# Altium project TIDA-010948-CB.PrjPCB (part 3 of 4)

## Sheet TIDA-010948-CB-PWM.SchDoc
size 431 x 279 mm; Date: Not shown in title block; ApprovedBy: Not shown in title block; CheckedBy: Not shown in title block; Author: Not shown in title block; CompanyName: Not shown in title block; Engineer: Not shown in title block; Organization: Not shown in title block; Address1: Not shown in title block; Address2: Not shown in title block; Address3: Not shown in title block; Address4: Not shown in title block; DocumentNumber: 7; Revision: Use project parameter SCH_Rev; SheetNumber: 7; SheetTotal: 11; PageSetup: Record=PageOptions¦CenterHorizontal=True¦CenterVertical=True¦PrintScale=1.00¦XCorrection=1.00¦YCorrection=1.00¦PrintKind=0¦BorderSize=5000000¦LeftOffset=0¦BottomOffset=0¦Orientation=2¦PaperLength=1000¦PaperWidth=1000¦Scale=100¦PaperSource=15¦PrintQuality=600¦MediaType=1¦DitherType=10¦PaperKind=Letter¦PrintScaleMode=1
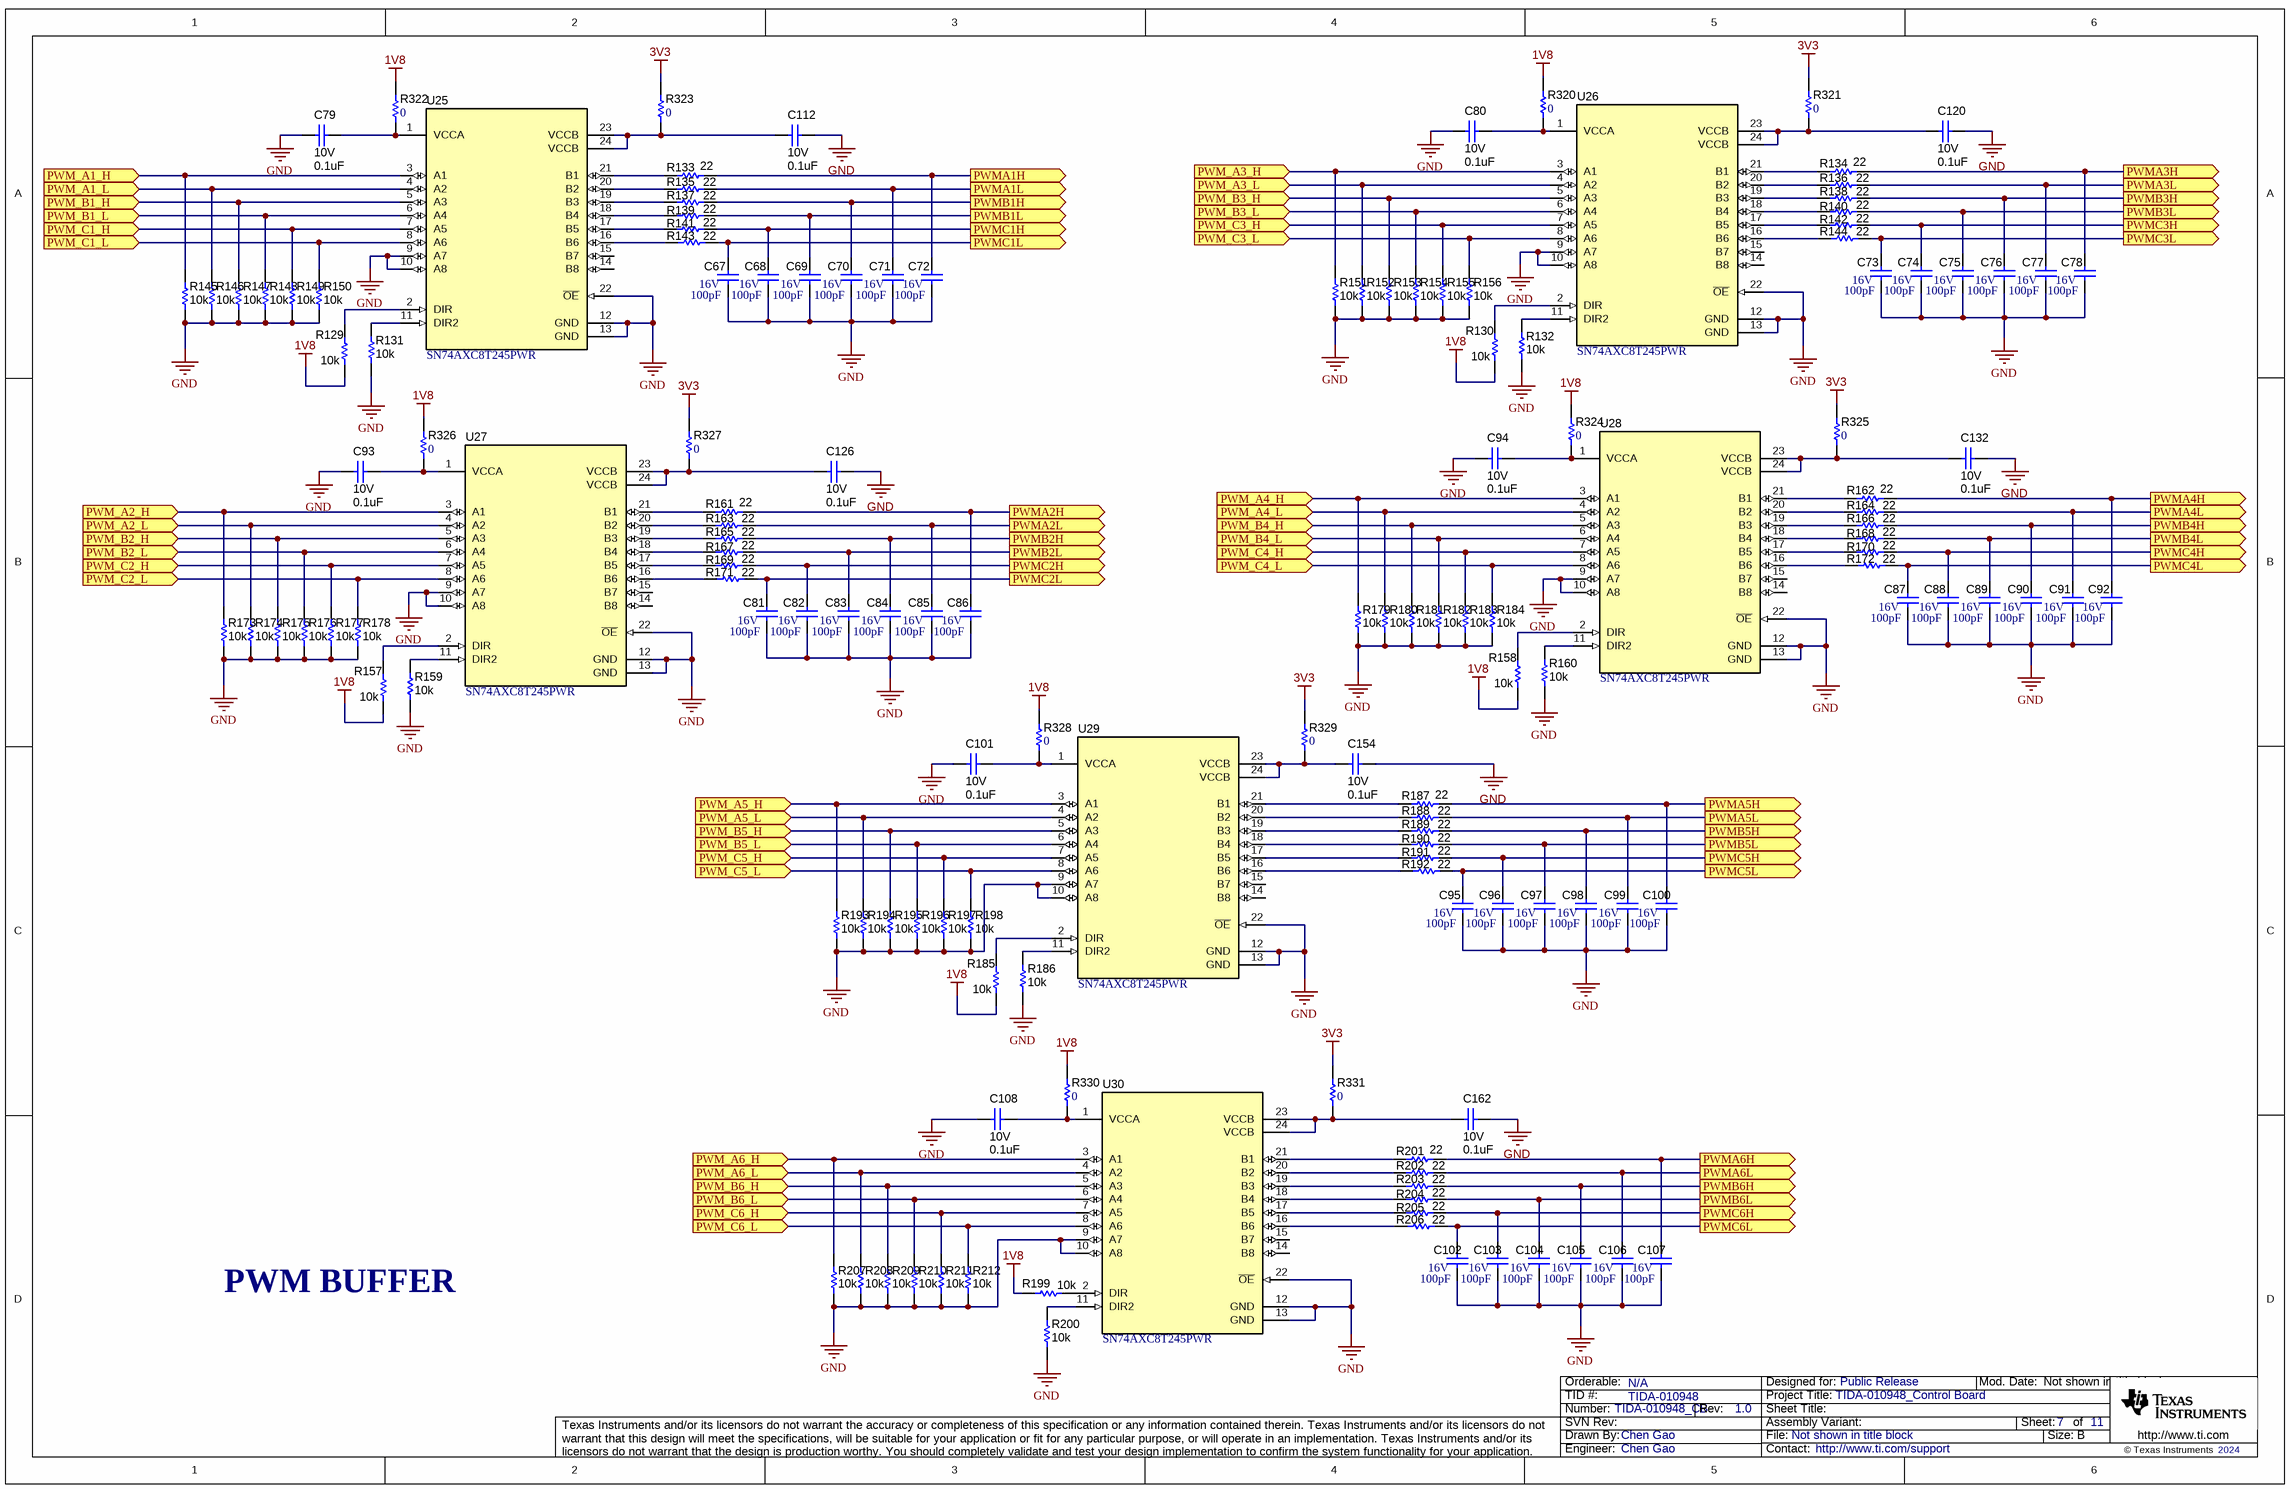
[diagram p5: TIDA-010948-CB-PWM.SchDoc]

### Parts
C67  VDC_V: 16V  ValueDisplayed: 100pF  [0402]  (hidden comment: 0402YC101KAT2A)
C68  VDC_V: 16V  ValueDisplayed: 100pF  [0402]  (hidden comment: 0402YC101KAT2A)
C69  VDC_V: 16V  ValueDisplayed: 100pF  [0402]  (hidden comment: 0402YC101KAT2A)
C70  VDC_V: 16V  ValueDisplayed: 100pF  [0402]  (hidden comment: 0402YC101KAT2A)
C71  VDC_V: 16V  ValueDisplayed: 100pF  [0402]  (hidden comment: 0402YC101KAT2A)
C72  VDC_V: 16V  ValueDisplayed: 100pF  [0402]  (hidden comment: 0402YC101KAT2A)
C73  VDC_V: 16V  ValueDisplayed: 100pF  [0402]  (hidden comment: 0402YC101KAT2A)
C74  VDC_V: 16V  ValueDisplayed: 100pF  [0402]  (hidden comment: 0402YC101KAT2A)
C75  VDC_V: 16V  ValueDisplayed: 100pF  [0402]  (hidden comment: 0402YC101KAT2A)
C76  VDC_V: 16V  ValueDisplayed: 100pF  [0402]  (hidden comment: 0402YC101KAT2A)
C77  VDC_V: 16V  ValueDisplayed: 100pF  [0402]  (hidden comment: 0402YC101KAT2A)
C78  VDC_V: 16V  ValueDisplayed: 100pF  [0402]  (hidden comment: 0402YC101KAT2A)
C79  VDC_V: 10V  ValueDisplayed: 0.1uF  [0402]  (hidden comment: GRM155R71A104KA01D)
C80  VDC_V: 10V  ValueDisplayed: 0.1uF  [0402]  (hidden comment: GRM155R71A104KA01D)
C81  VDC_V: 16V  ValueDisplayed: 100pF  [0402]  (hidden comment: 0402YC101KAT2A)
C82  VDC_V: 16V  ValueDisplayed: 100pF  [0402]  (hidden comment: 0402YC101KAT2A)
C83  VDC_V: 16V  ValueDisplayed: 100pF  [0402]  (hidden comment: 0402YC101KAT2A)
C84  VDC_V: 16V  ValueDisplayed: 100pF  [0402]  (hidden comment: 0402YC101KAT2A)
C85  VDC_V: 16V  ValueDisplayed: 100pF  [0402]  (hidden comment: 0402YC101KAT2A)
C86  VDC_V: 16V  ValueDisplayed: 100pF  [0402]  (hidden comment: 0402YC101KAT2A)
C87  VDC_V: 16V  ValueDisplayed: 100pF  [0402]  (hidden comment: 0402YC101KAT2A)
C88  VDC_V: 16V  ValueDisplayed: 100pF  [0402]  (hidden comment: 0402YC101KAT2A)
C89  VDC_V: 16V  ValueDisplayed: 100pF  [0402]  (hidden comment: 0402YC101KAT2A)
C90  VDC_V: 16V  ValueDisplayed: 100pF  [0402]  (hidden comment: 0402YC101KAT2A)
C91  VDC_V: 16V  ValueDisplayed: 100pF  [0402]  (hidden comment: 0402YC101KAT2A)
C92  VDC_V: 16V  ValueDisplayed: 100pF  [0402]  (hidden comment: 0402YC101KAT2A)
C93  VDC_V: 10V  ValueDisplayed: 0.1uF  [0402]  (hidden comment: GRM155R71A104KA01D)
C94  VDC_V: 10V  ValueDisplayed: 0.1uF  [0402]  (hidden comment: GRM155R71A104KA01D)
C95  VDC_V: 16V  ValueDisplayed: 100pF  [0402]  (hidden comment: 0402YC101KAT2A)
C96  VDC_V: 16V  ValueDisplayed: 100pF  [0402]  (hidden comment: 0402YC101KAT2A)
C97  VDC_V: 16V  ValueDisplayed: 100pF  [0402]  (hidden comment: 0402YC101KAT2A)
C98  VDC_V: 16V  ValueDisplayed: 100pF  [0402]  (hidden comment: 0402YC101KAT2A)
C99  VDC_V: 16V  ValueDisplayed: 100pF  [0402]  (hidden comment: 0402YC101KAT2A)
C100  VDC_V: 16V  ValueDisplayed: 100pF  [0402]  (hidden comment: 0402YC101KAT2A)
C101  VDC_V: 10V  ValueDisplayed: 0.1uF  [0402]  (hidden comment: GRM155R71A104KA01D)
C102  VDC_V: 16V  ValueDisplayed: 100pF  [0402]  (hidden comment: 0402YC101KAT2A)
C103  VDC_V: 16V  ValueDisplayed: 100pF  [0402]  (hidden comment: 0402YC101KAT2A)
C104  VDC_V: 16V  ValueDisplayed: 100pF  [0402]  (hidden comment: 0402YC101KAT2A)
C105  VDC_V: 16V  ValueDisplayed: 100pF  [0402]  (hidden comment: 0402YC101KAT2A)
C106  VDC_V: 16V  ValueDisplayed: 100pF  [0402]  (hidden comment: 0402YC101KAT2A)
C107  VDC_V: 16V  ValueDisplayed: 100pF  [0402]  (hidden comment: 0402YC101KAT2A)
C108  VDC_V: 10V  ValueDisplayed: 0.1uF  [0402]  (hidden comment: GRM155R71A104KA01D)
C112  VDC_V: 10V  ValueDisplayed: 0.1uF  [0402]  (hidden comment: GRM155R71A104KA01D)
C120  VDC_V: 10V  ValueDisplayed: 0.1uF  [0402]  (hidden comment: GRM155R71A104KA01D)
C126  VDC_V: 10V  ValueDisplayed: 0.1uF  [0402]  (hidden comment: GRM155R71A104KA01D)
C132  VDC_V: 10V  ValueDisplayed: 0.1uF  [0402]  (hidden comment: GRM155R71A104KA01D)
C154  VDC_V: 10V  ValueDisplayed: 0.1uF  [0402]  (hidden comment: GRM155R71A104KA01D)
C162  VDC_V: 10V  ValueDisplayed: 0.1uF  [0402]  (hidden comment: GRM155R71A104KA01D)
R129  ValueDisplayed: 10k  [0402]  (hidden comment: Resistor)
R130  ValueDisplayed: 10k  [0402]  (hidden comment: Resistor)
R131  ValueDisplayed: 10k  [0402]  (hidden comment: Resistor)
R132  ValueDisplayed: 10k  [0402]  (hidden comment: Resistor)
R133  ValueDisplayed: 22  [0402]  (hidden comment: CRCW040222R0JNED)
R134  ValueDisplayed: 22  [0402]  (hidden comment: CRCW040222R0JNED)
R135  ValueDisplayed: 22  [0402]  (hidden comment: CRCW040222R0JNED)
R136  ValueDisplayed: 22  [0402]  (hidden comment: CRCW040222R0JNED)
R137  ValueDisplayed: 22  [0402]  (hidden comment: CRCW040222R0JNED)
R138  ValueDisplayed: 22  [0402]  (hidden comment: CRCW040222R0JNED)
R139  ValueDisplayed: 22  [0402]  (hidden comment: CRCW040222R0JNED)
R140  ValueDisplayed: 22  [0402]  (hidden comment: CRCW040222R0JNED)
R141  ValueDisplayed: 22  [0402]  (hidden comment: CRCW040222R0JNED)
R142  ValueDisplayed: 22  [0402]  (hidden comment: CRCW040222R0JNED)
R143  ValueDisplayed: 22  [0402]  (hidden comment: CRCW040222R0JNED)
R144  ValueDisplayed: 22  [0402]  (hidden comment: CRCW040222R0JNED)
R145  ValueDisplayed: 10k  [0402]  (hidden comment: Resistor)
R146  ValueDisplayed: 10k  [0402]  (hidden comment: Resistor)
R147  ValueDisplayed: 10k  [0402]  (hidden comment: Resistor)
R148  ValueDisplayed: 10k  [0402]  (hidden comment: Resistor)
R149  ValueDisplayed: 10k  [0402]  (hidden comment: Resistor)
R150  ValueDisplayed: 10k  [0402]  (hidden comment: Resistor)
R151  ValueDisplayed: 10k  [0402]  (hidden comment: Resistor)
R152  ValueDisplayed: 10k  [0402]  (hidden comment: Resistor)
R153  ValueDisplayed: 10k  [0402]  (hidden comment: Resistor)
R154  ValueDisplayed: 10k  [0402]  (hidden comment: Resistor)
R155  ValueDisplayed: 10k  [0402]  (hidden comment: Resistor)
R156  ValueDisplayed: 10k  [0402]  (hidden comment: Resistor)
R157  ValueDisplayed: 10k  [0402]  (hidden comment: Resistor)
R158  ValueDisplayed: 10k  [0402]  (hidden comment: Resistor)
R159  ValueDisplayed: 10k  [0402]  (hidden comment: Resistor)
R160  ValueDisplayed: 10k  [0402]  (hidden comment: Resistor)
R161  ValueDisplayed: 22  [0402]  (hidden comment: CRCW040222R0JNED)
R162  ValueDisplayed: 22  [0402]  (hidden comment: CRCW040222R0JNED)
R163  ValueDisplayed: 22  [0402]  (hidden comment: CRCW040222R0JNED)
R164  ValueDisplayed: 22  [0402]  (hidden comment: CRCW040222R0JNED)
R165  ValueDisplayed: 22  [0402]  (hidden comment: CRCW040222R0JNED)
R166  ValueDisplayed: 22  [0402]  (hidden comment: CRCW040222R0JNED)
R167  ValueDisplayed: 22  [0402]  (hidden comment: CRCW040222R0JNED)
R168  ValueDisplayed: 22  [0402]  (hidden comment: CRCW040222R0JNED)
R169  ValueDisplayed: 22  [0402]  (hidden comment: CRCW040222R0JNED)
R170  ValueDisplayed: 22  [0402]  (hidden comment: CRCW040222R0JNED)
R171  ValueDisplayed: 22  [0402]  (hidden comment: CRCW040222R0JNED)
R172  ValueDisplayed: 22  [0402]  (hidden comment: CRCW040222R0JNED)
R173  ValueDisplayed: 10k  [0402]  (hidden comment: Resistor)
R174  ValueDisplayed: 10k  [0402]  (hidden comment: Resistor)
R175  ValueDisplayed: 10k  [0402]  (hidden comment: Resistor)
R176  ValueDisplayed: 10k  [0402]  (hidden comment: Resistor)
R177  ValueDisplayed: 10k  [0402]  (hidden comment: Resistor)
R178  ValueDisplayed: 10k  [0402]  (hidden comment: Resistor)
R179  ValueDisplayed: 10k  [0402]  (hidden comment: Resistor)
R180  ValueDisplayed: 10k  [0402]  (hidden comment: Resistor)
R181  ValueDisplayed: 10k  [0402]  (hidden comment: Resistor)
R182  ValueDisplayed: 10k  [0402]  (hidden comment: Resistor)
R183  ValueDisplayed: 10k  [0402]  (hidden comment: Resistor)
R184  ValueDisplayed: 10k  [0402]  (hidden comment: Resistor)
R185  ValueDisplayed: 10k  [0402]  (hidden comment: Resistor)
R186  ValueDisplayed: 10k  [0402]  (hidden comment: Resistor)
R187  ValueDisplayed: 22  [0402]  (hidden comment: CRCW040222R0JNED)
R188  ValueDisplayed: 22  [0402]  (hidden comment: CRCW040222R0JNED)
R189  ValueDisplayed: 22  [0402]  (hidden comment: CRCW040222R0JNED)
R190  ValueDisplayed: 22  [0402]  (hidden comment: CRCW040222R0JNED)
R191  ValueDisplayed: 22  [0402]  (hidden comment: CRCW040222R0JNED)
R192  ValueDisplayed: 22  [0402]  (hidden comment: CRCW040222R0JNED)
R193  ValueDisplayed: 10k  [0402]  (hidden comment: Resistor)
R194  ValueDisplayed: 10k  [0402]  (hidden comment: Resistor)
R195  ValueDisplayed: 10k  [0402]  (hidden comment: Resistor)
R196  ValueDisplayed: 10k  [0402]  (hidden comment: Resistor)
R197  ValueDisplayed: 10k  [0402]  (hidden comment: Resistor)
R198  ValueDisplayed: 10k  [0402]  (hidden comment: Resistor)
R199  ValueDisplayed: 10k  [0402]  (hidden comment: Resistor)
R200  ValueDisplayed: 10k  [0402]  (hidden comment: Resistor)
R201  ValueDisplayed: 22  [0402]  (hidden comment: CRCW040222R0JNED)
R202  ValueDisplayed: 22  [0402]  (hidden comment: CRCW040222R0JNED)
R203  ValueDisplayed: 22  [0402]  (hidden comment: CRCW040222R0JNED)
R204  ValueDisplayed: 22  [0402]  (hidden comment: CRCW040222R0JNED)
R205  ValueDisplayed: 22  [0402]  (hidden comment: CRCW040222R0JNED)
R206  ValueDisplayed: 22  [0402]  (hidden comment: CRCW040222R0JNED)
R207  ValueDisplayed: 10k  [0402]  (hidden comment: Resistor)
R208  ValueDisplayed: 10k  [0402]  (hidden comment: Resistor)
R209  ValueDisplayed: 10k  [0402]  (hidden comment: Resistor)
R210  ValueDisplayed: 10k  [0402]  (hidden comment: Resistor)
R211  ValueDisplayed: 10k  [0402]  (hidden comment: Resistor)
R212  ValueDisplayed: 10k  [0402]  (hidden comment: Resistor)
R320  ValueDisplayed: 0  [0402L]  (hidden comment: ERJ-2GE0R00X)
R321  ValueDisplayed: 0  [0402L]  (hidden comment: ERJ-2GE0R00X)
R322  ValueDisplayed: 0  [0402L]  (hidden comment: ERJ-2GE0R00X)
R323  ValueDisplayed: 0  [0402L]  (hidden comment: ERJ-2GE0R00X)
R324  ValueDisplayed: 0  [0402L]  (hidden comment: ERJ-2GE0R00X)
R325  ValueDisplayed: 0  [0402L]  (hidden comment: ERJ-2GE0R00X)
R326  ValueDisplayed: 0  [0402L]  (hidden comment: ERJ-2GE0R00X)
R327  ValueDisplayed: 0  [0402L]  (hidden comment: ERJ-2GE0R00X)
R328  ValueDisplayed: 0  [0402L]  (hidden comment: ERJ-2GE0R00X)
R329  ValueDisplayed: 0  [0402L]  (hidden comment: ERJ-2GE0R00X)
R330  ValueDisplayed: 0  [0402L]  (hidden comment: ERJ-2GE0R00X)
R331  ValueDisplayed: 0  [0402L]  (hidden comment: ERJ-2GE0R00X)
U25  SN74AXC8T245PWR  [PW0024A_N]
U26  SN74AXC8T245PWR  [PW0024A_N]
U27  SN74AXC8T245PWR  [PW0024A_N]
U28  SN74AXC8T245PWR  [PW0024A_N]
U29  SN74AXC8T245PWR  [PW0024A_N]
U30  SN74AXC8T245PWR  [PW0024A_N]

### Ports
PWM_A1_H (in), PWM_A1_L (in), PWM_A2_H (in), PWM_A2_L (in), PWM_A3_H (in), PWM_A3_L (in), PWM_A4_H (in), PWM_A4_L (in), PWM_A5_H (in), PWM_A5_L (in), PWM_A6_H (in), PWM_A6_L (in), PWM_B1_H (in), PWM_B1_L (in), PWM_B2_H (in), PWM_B2_L (in), PWM_B3_H (in), PWM_B3_L (in), PWM_B4_H (in), PWM_B4_L (in), PWM_B5_H (in), PWM_B5_L (in), PWM_B6_H (in), PWM_B6_L (in), PWM_C1_H (in), PWM_C1_L (in), PWM_C2_H (in), PWM_C2_L (in), PWM_C3_H (in), PWM_C3_L (in), PWM_C4_H (in), PWM_C4_L (in), PWM_C5_H (in), PWM_C5_L (in), PWM_C6_H (in), PWM_C6_L (in), PWMA1H (out), PWMA1L (out), PWMA2H (out), PWMA2L (out), PWMA3H (out), PWMA3L (out), PWMA4H (out), PWMA4L (out), PWMA5H (out), PWMA5L (out), PWMA6H (out), PWMA6L (out), PWMB1H (out), PWMB1L (out), PWMB2H (out), PWMB2L (out), PWMB3H (out), PWMB3L (out), PWMB4H (out), PWMB4L (out), PWMB5H (out), PWMB5L (out), PWMB6H (out), PWMB6L (out), PWMC1H (out), PWMC1L (out), PWMC2H (out), PWMC2L (out), PWMC3H (out), PWMC3L (out), PWMC4H (out), PWMC4L (out), PWMC5H (out), PWMC5L (out), PWMC6H (out), PWMC6L (out)

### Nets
1V8: R129.1 R130.1 R157.1 R158.1 R185.1 R199.1 R320.2 R322.2 R324.2 R326.2 R328.2 R330.2
3V3: R321.2 R323.2 R325.2 R327.2 R329.2 R331.2
GND: C67.2 C68.2 C69.2 C70.2 C71.2 C72.2 C73.2 C74.2 C75.2 C76.2 C77.2 C78.2 C79.1 C80.1 C81.2 C82.2 C83.2 C84.2 C85.2 C86.2 C87.2 C88.2 C89.2 C90.2 C91.2 C92.2 C93.1 C94.1 C95.2 C96.2 C97.2 C98.2 C99.2 C100.2 C101.1 C102.2 C103.2 C104.2 C105.2 C106.2 C107.2 C108.1 C112.2 C120.2 C126.2 C132.2 C154.2 C162.2 R131.2 R132.2 R145.2 R146.2 R147.2 R148.2 R149.2 R150.2 R151.2 R152.2 R153.2 R154.2 R155.2 R156.2 R159.2 R160.2 R173.2 R174.2 R175.2 R176.2 R177.2 R178.2 R179.2 R180.2 R181.2 R182.2 R183.2 R184.2 R186.2 R193.2 R194.2 R195.2 R196.2 R197.2 R198.2 R200.2 R207.2 R208.2 R209.2 R210.2 R211.2 R212.2 U25.9(A7) U25.10(A8) U25.12(GND) U25.13(GND) U25.22(~{OE}) U26.9(A7) U26.10(A8) U26.12(GND) U26.13(GND) U26.22(~{OE}) U27.9(A7) U27.10(A8) U27.12(GND) U27.13(GND) U27.22(~{OE}) U28.9(A7) U28.10(A8) U28.12(GND) U28.13(GND) U28.22(~{OE}) U29.9(A7) U29.10(A8) U29.12(GND) U29.13(GND) U29.22(~{OE}) U30.9(A7) U30.10(A8) U30.12(GND) U30.13(GND) U30.22(~{OE})
PWM_A1_H: R145.1 U25.3(A1) ; port PWM_A1_H
PWM_A1_L: R146.1 U25.4(A2) ; port PWM_A1_L
PWM_A2_H: R173.1 U27.3(A1) ; port PWM_A2_H
PWM_A2_L: R174.1 U27.4(A2) ; port PWM_A2_L
PWM_A3_H: R151.1 U26.3(A1) ; port PWM_A3_H
PWM_A3_L: R152.1 U26.4(A2) ; port PWM_A3_L
PWM_A4_H: R179.1 U28.3(A1) ; port PWM_A4_H
PWM_A4_L: R180.1 U28.4(A2) ; port PWM_A4_L
PWM_A5_H: R193.1 U29.3(A1) ; port PWM_A5_H
PWM_A5_L: R194.1 U29.4(A2) ; port PWM_A5_L
PWM_A6_H: R207.1 U30.3(A1) ; port PWM_A6_H
PWM_A6_L: R208.1 U30.4(A2) ; port PWM_A6_L
PWM_B1_H: R147.1 U25.5(A3) ; port PWM_B1_H
PWM_B1_L: R148.1 U25.6(A4) ; port PWM_B1_L
PWM_B2_H: R175.1 U27.5(A3) ; port PWM_B2_H
PWM_B2_L: R176.1 U27.6(A4) ; port PWM_B2_L
PWM_B3_H: R153.1 U26.5(A3) ; port PWM_B3_H
PWM_B3_L: R154.1 U26.6(A4) ; port PWM_B3_L
PWM_B4_H: R181.1 U28.5(A3) ; port PWM_B4_H
PWM_B4_L: R182.1 U28.6(A4) ; port PWM_B4_L
PWM_B5_H: R195.1 U29.5(A3) ; port PWM_B5_H
PWM_B5_L: R196.1 U29.6(A4) ; port PWM_B5_L
PWM_B6_H: R209.1 U30.5(A3) ; port PWM_B6_H
PWM_B6_L: R210.1 U30.6(A4) ; port PWM_B6_L
PWM_C1_H: R149.1 U25.7(A5) ; port PWM_C1_H
PWM_C1_L: R150.1 U25.8(A6) ; port PWM_C1_L
PWM_C2_H: R177.1 U27.7(A5) ; port PWM_C2_H
PWM_C2_L: R178.1 U27.8(A6) ; port PWM_C2_L
PWM_C3_H: R155.1 U26.7(A5) ; port PWM_C3_H
PWM_C3_L: R156.1 U26.8(A6) ; port PWM_C3_L
PWM_C4_H: R183.1 U28.7(A5) ; port PWM_C4_H
PWM_C4_L: R184.1 U28.8(A6) ; port PWM_C4_L
PWM_C5_H: R197.1 U29.7(A5) ; port PWM_C5_H
PWM_C5_L: R198.1 U29.8(A6) ; port PWM_C5_L
PWM_C6_H: R211.1 U30.7(A5) ; port PWM_C6_H
PWM_C6_L: R212.1 U30.8(A6) ; port PWM_C6_L
PWMA1H: C72.1 R133.2 ; port PWMA1H
PWMA1L: C71.1 R135.2 ; port PWMA1L
PWMA2H: C86.1 R161.2 ; port PWMA2H
PWMA2L: C85.1 R163.2 ; port PWMA2L
PWMA3H: C78.1 R134.2 ; port PWMA3H
PWMA3L: C77.1 R136.2 ; port PWMA3L
PWMA4H: C92.1 R162.2 ; port PWMA4H
PWMA4L: C91.1 R164.2 ; port PWMA4L
PWMA5H: C100.1 R187.2 ; port PWMA5H
PWMA5L: C99.1 R188.2 ; port PWMA5L
PWMA6H: C107.1 R201.2 ; port PWMA6H
PWMA6L: C106.1 R202.2 ; port PWMA6L
PWMB1H: C70.1 R137.2 ; port PWMB1H
PWMB1L: C69.1 R139.2 ; port PWMB1L
PWMB2H: C84.1 R165.2 ; port PWMB2H
PWMB2L: C83.1 R167.2 ; port PWMB2L
PWMB3H: C76.1 R138.2 ; port PWMB3H
PWMB3L: C75.1 R140.2 ; port PWMB3L
PWMB4H: C90.1 R166.2 ; port PWMB4H
PWMB4L: C89.1 R168.2 ; port PWMB4L
PWMB5H: C98.1 R189.2 ; port PWMB5H
PWMB5L: C97.1 R190.2 ; port PWMB5L
PWMB6H: C105.1 R203.2 ; port PWMB6H
PWMB6L: C104.1 R204.2 ; port PWMB6L
PWMC1H: C68.1 R141.2 ; port PWMC1H
PWMC1L: C67.1 R143.2 ; port PWMC1L
PWMC2H: C82.1 R169.2 ; port PWMC2H
PWMC2L: C81.1 R171.2 ; port PWMC2L
PWMC3H: C74.1 R142.2 ; port PWMC3H
PWMC3L: C73.1 R144.2 ; port PWMC3L
PWMC4H: C88.1 R170.2 ; port PWMC4H
PWMC4L: C87.1 R172.2 ; port PWMC4L
PWMC5H: C96.1 R191.2 ; port PWMC5H
PWMC5L: C95.1 R192.2 ; port PWMC5L
PWMC6H: C103.1 R205.2 ; port PWMC6H
PWMC6L: C102.1 R206.2 ; port PWMC6L
NetC79_2: C79.2 R322.1 U25.1(VCCA)
NetC80_2: C80.2 R320.1 U26.1(VCCA)
NetC93_2: C93.2 R326.1 U27.1(VCCA)
NetC94_2: C94.2 R324.1 U28.1(VCCA)
NetC101_2: C101.2 R328.1 U29.1(VCCA)
NetC108_2: C108.2 R330.1 U30.1(VCCA)
NetC112_1: C112.1 R323.1 U25.23(VCCB) U25.24(VCCB)
NetC120_1: C120.1 R321.1 U26.23(VCCB) U26.24(VCCB)
NetC126_1: C126.1 R327.1 U27.23(VCCB) U27.24(VCCB)
NetC132_1: C132.1 R325.1 U28.23(VCCB) U28.24(VCCB)
NetC154_1: C154.1 R329.1 U29.23(VCCB) U29.24(VCCB)
NetC162_1: C162.1 R331.1 U30.23(VCCB) U30.24(VCCB)
NetR129_2: R129.2 U25.2(DIR)
NetR130_2: R130.2 U26.2(DIR)
NetR131_1: R131.1 U25.11(DIR2)
NetR132_1: R132.1 U26.11(DIR2)
NetR133_1: R133.1 U25.21(B1)
NetR134_1: R134.1 U26.21(B1)
NetR135_1: R135.1 U25.20(B2)
NetR136_1: R136.1 U26.20(B2)
NetR137_1: R137.1 U25.19(B3)
NetR138_1: R138.1 U26.19(B3)
NetR139_1: R139.1 U25.18(B4)
NetR140_1: R140.1 U26.18(B4)
NetR141_1: R141.1 U25.17(B5)
NetR142_1: R142.1 U26.17(B5)
NetR143_1: R143.1 U25.16(B6)
NetR144_1: R144.1 U26.16(B6)
NetR157_2: R157.2 U27.2(DIR)
NetR158_2: R158.2 U28.2(DIR)
NetR159_1: R159.1 U27.11(DIR2)
NetR160_1: R160.1 U28.11(DIR2)
NetR161_1: R161.1 U27.21(B1)
NetR162_1: R162.1 U28.21(B1)
NetR163_1: R163.1 U27.20(B2)
NetR164_1: R164.1 U28.20(B2)
NetR165_1: R165.1 U27.19(B3)
NetR166_1: R166.1 U28.19(B3)
NetR167_1: R167.1 U27.18(B4)
NetR168_1: R168.1 U28.18(B4)
NetR169_1: R169.1 U27.17(B5)
NetR170_1: R170.1 U28.17(B5)
NetR171_1: R171.1 U27.16(B6)
NetR172_1: R172.1 U28.16(B6)
NetR185_2: R185.2 U29.2(DIR)
NetR186_1: R186.1 U29.11(DIR2)
NetR187_1: R187.1 U29.21(B1)
NetR188_1: R188.1 U29.20(B2)
NetR189_1: R189.1 U29.19(B3)
NetR190_1: R190.1 U29.18(B4)
NetR191_1: R191.1 U29.17(B5)
NetR192_1: R192.1 U29.16(B6)
NetR199_2: R199.2 U30.2(DIR)
NetR200_1: R200.1 U30.11(DIR2)
NetR201_1: R201.1 U30.21(B1)
NetR202_1: R202.1 U30.20(B2)
NetR203_1: R203.1 U30.19(B3)
NetR204_1: R204.1 U30.18(B4)
NetR205_1: R205.1 U30.17(B5)
NetR206_1: R206.1 U30.16(B6)

Not connected (* = marked no-connect by the designer): U25 14(B8) 15(B7); U26 14(B8) 15(B7); U27 14(B8) 15(B7); U28 14(B8) 15(B7); U29 14(B8) 15(B7); U30 14(B8) 15(B7)

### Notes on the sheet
- PWM BUFFER

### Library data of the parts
C67-C78 C81-C92 C95-C100 C102-C107 = CMP-0006200-2: CAP, CERM, 100 pF, 16 V, +/- 10%, X7R, 0402; Manufacturer: AVX; TaMin_C: -55°C; Polarized: N; SizeAreaWB_mm2: 3; Value1: Unknown; U/M: EA; Value: 100pF; TaMax_C: 125°C; SizeZ_mm: 0.6; SizeX_mm: 1; SizeY_mm: 0.5; AEC Category: Q200
C79 C80 C93 C94 C101 C108 C112 C120 C126 C132 C154 C162 = CMP-0006629-2: CAP, CERM, 0.1 uF, 10 V, +/- 10%, X7R, 0402; Manufacturer: MuRata; TaMin_C: -55°C; Polarized: N; SizeAreaWB_mm2: 3; Value1: Unknown; U/M: EA; Value: 0.1uF; TaMax_C: 125°C; SizeZ_mm: 0.6; SizeX_mm: 1; SizeY_mm: 0.5; Cap_F: 100nF; AEC Category: Q200
R129-R132 R145-R160 R173-R186 R193-R200 R207-R212 = CMP-0026825-5: RES, 10 k, 5%, 0.063 W, AEC-Q200 Grade 0, 0402; PartNumber: CRCW040210K0JNED; Manufacturer: Vishay-Dale; Value: 10k; Value_Code: 10k0; Power_W: 63mW; Value2: 0.063W; VDC_V: 50V; TempCo: 200 ppm/C; EIA_Code: E24; AEC Category: Q200; AEC Grade: 0; AEC Qualified: Y; SizeArea_mm2: 0.5; SizeX_mm: 1; SizeZ_mm: 0.6
R133-R144 R161-R172 R187-R192 R201-R206 = CMP-0026880-3: RES, 22, 5%, 0.063 W, AEC-Q200 Grade 0, 0402; Manufacturer: Vishay-Dale; Power_W: 63mW; TempCo: 200 ppm/C; Value_Code: 22R0; Value: 22; EIA_Code: E24; SizeX_mm: 1; SizeY_mm: 0.5; SizeZ_mm: 0.6; Value2: 0.063W; AEC Qualified: Y; VDC_V: 50V; AEC Category: Q200; AEC Grade: 0
R320-R331 = CMP-0026992-3: RES, 0, 5%, 0.1 W, AEC-Q200 Grade 0, 0402; Manufacturer: Panasonic; Power_W: 100mW; TempCo: 600 ppm/C; Value_Code: 0000; Value: 0; EIA_Code: E24; SizeX_mm: 1; SizeY_mm: 0.5; SizeZ_mm: 0.6; Value2: 0.1W; AEC Qualified: Y; VDC_V: 50V; AEC Category: Q200; SizeAreaWB_mm2: 3
U25-U30 = CMP-0065205-4: Asynchronous Communication Between Data Buses, PW0024A (TSSOP-24); Manufacturer: Texas Instruments; Alternate PartNumber: SN74AXC8T245PWT; SizeX_mm: 6.4; SizeY_mm: 7.8; CompType: IC; SizeZ_mm: 1.2; SizeArea_mm2: 49.92; SizeAreaWB_mm2: 82.32; AEC Category: Q200; AEC Qualified: N; Rating: Catalog

## Sheet TIDA-010948-CB-Ethernet1.SchDoc
size 431 x 279 mm; Date: Not shown in title block; ApprovedBy: Not shown in title block; CheckedBy: Not shown in title block; Author: Not shown in title block; CompanyName: Not shown in title block; Engineer: Not shown in title block; Organization: Not shown in title block; Address1: Not shown in title block; Address2: Not shown in title block; Address3: Not shown in title block; Address4: Not shown in title block; DocumentNumber: 8; Revision: Use project parameter SCH_Rev; SheetNumber: 8; SheetTotal: 11; PageSetup: Record=PageOptions¦CenterHorizontal=True¦CenterVertical=True¦PrintScale=1.00¦XCorrection=1.00¦YCorrection=1.00¦PrintKind=0¦BorderSize=5000000¦LeftOffset=0¦BottomOffset=0¦Orientation=2¦PaperLength=1000¦PaperWidth=1000¦Scale=100¦PaperSource=15¦PrintQuality=600¦MediaType=1¦DitherType=10¦PaperKind=Letter¦PrintScaleMode=1
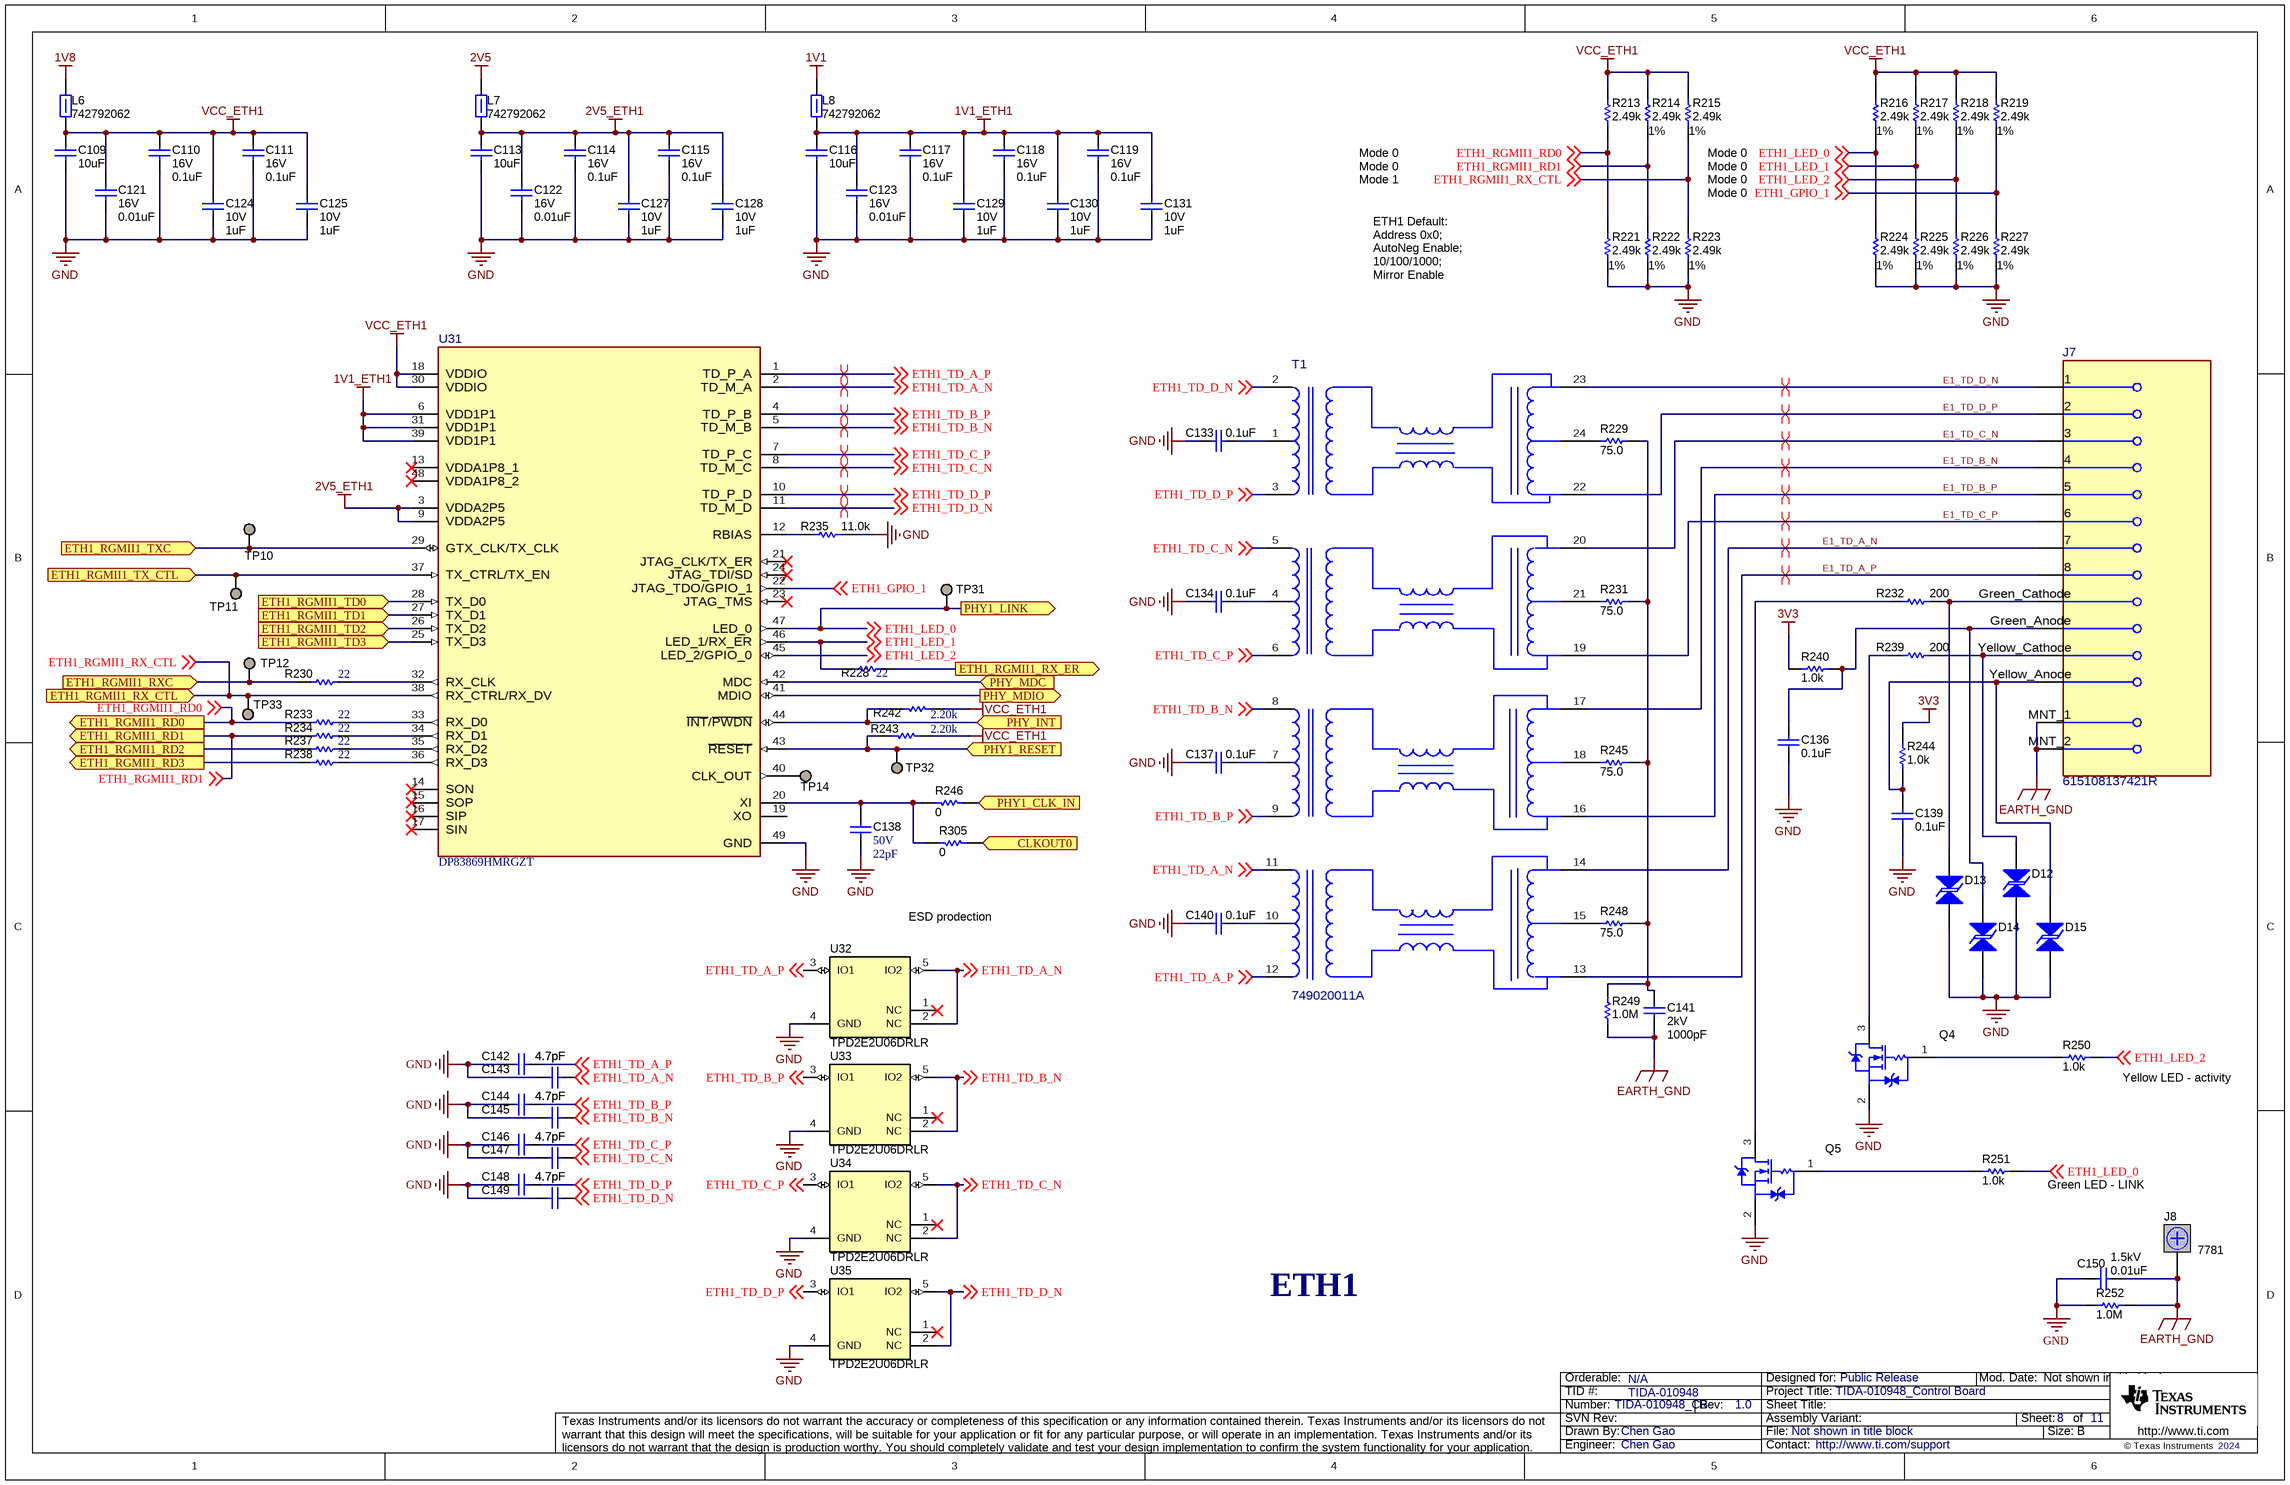
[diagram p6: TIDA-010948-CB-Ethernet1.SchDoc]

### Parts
C109  ValueDisplayed: 10uF  [1206_190]  (hidden comment: C3216X7R1V106M160AC)
C110  VDC_V: 16V  ValueDisplayed: 0.1uF  [0201_033]  (hidden comment: GRM033C71C104KE14D)
C111  VDC_V: 16V  ValueDisplayed: 0.1uF  [0201_033]  (hidden comment: GRM033C71C104KE14D)
C113  ValueDisplayed: 10uF  [1206_190]  (hidden comment: C3216X7R1V106M160AC)
C114  VDC_V: 16V  ValueDisplayed: 0.1uF  [0201_033]  (hidden comment: GRM033C71C104KE14D)
C115  VDC_V: 16V  ValueDisplayed: 0.1uF  [0201_033]  (hidden comment: GRM033C71C104KE14D)
C116  ValueDisplayed: 10uF  [1206_190]  (hidden comment: C3216X7R1V106M160AC)
C117  VDC_V: 16V  ValueDisplayed: 0.1uF  [0201_033]  (hidden comment: GRM033C71C104KE14D)
C118  VDC_V: 16V  ValueDisplayed: 0.1uF  [0201_033]  (hidden comment: GRM033C71C104KE14D)
C119  VDC_V: 16V  ValueDisplayed: 0.1uF  [0201_033]  (hidden comment: GRM033C71C104KE14D)
C121  VDC_V: 16V  ValueDisplayed: 0.01uF  [0402]  (hidden comment: 885012205031)
C122  VDC_V: 16V  ValueDisplayed: 0.01uF  [0402]  (hidden comment: 885012205031)
C123  VDC_V: 16V  ValueDisplayed: 0.01uF  [0402]  (hidden comment: 885012205031)
C124  VDC_V: 10V  ValueDisplayed: 1uF  [0201]  (hidden comment: GRM033R61A105ME15D)
C125  VDC_V: 10V  ValueDisplayed: 1uF  [0201]  (hidden comment: GRM033R61A105ME15D)
C127  VDC_V: 10V  ValueDisplayed: 1uF  [0201]  (hidden comment: GRM033R61A105ME15D)
C128  VDC_V: 10V  ValueDisplayed: 1uF  [0201]  (hidden comment: GRM033R61A105ME15D)
C129  VDC_V: 10V  ValueDisplayed: 1uF  [0201]  (hidden comment: GRM033R61A105ME15D)
C130  VDC_V: 10V  ValueDisplayed: 1uF  [0201]  (hidden comment: GRM033R61A105ME15D)
C131  VDC_V: 10V  ValueDisplayed: 1uF  [0201]  (hidden comment: GRM033R61A105ME15D)
C133  ValueDisplayed: 0.1uF  [0402]  (hidden comment: GRM155R71C104KA88D)
C134  ValueDisplayed: 0.1uF  [0402]  (hidden comment: GRM155R71C104KA88D)
C136  ValueDisplayed: 0.1uF  [0402]  (hidden comment: 885012105010)
C137  ValueDisplayed: 0.1uF  [0402]  (hidden comment: GRM155R71C104KA88D)
C138  VDC_V: 50V  ValueDisplayed: 22pF  [0402L]  (hidden comment: CGA2B2NP01H220J050BA)
C139  ValueDisplayed: 0.1uF  [0402]  (hidden comment: 885012105010)
C140  ValueDisplayed: 0.1uF  [0402]  (hidden comment: GRM155R71C104KA88D)
C141  VDC_V: 2kV  ValueDisplayed: 1000pF  [1808]  (hidden comment: GR442QR73D102KW01L)
C142  ValueDisplayed: 4.7pF  [0201L]  (hidden comment: GRM0335C1H4R7CA01D)
C143  ValueDisplayed: 4.7pF  [0201L]  (hidden comment: GRM0335C1H4R7CA01D)
C144  ValueDisplayed: 4.7pF  [0201L]  (hidden comment: GRM0335C1H4R7CA01D)
C145  ValueDisplayed: 4.7pF  [0201L]  (hidden comment: GRM0335C1H4R7CA01D)
C146  ValueDisplayed: 4.7pF  [0201L]  (hidden comment: GRM0335C1H4R7CA01D)
C147  ValueDisplayed: 4.7pF  [0201L]  (hidden comment: GRM0335C1H4R7CA01D)
C148  ValueDisplayed: 4.7pF  [0201L]  (hidden comment: GRM0335C1H4R7CA01D)
C149  ValueDisplayed: 4.7pF  [0201L]  (hidden comment: GRM0335C1H4R7CA01D)
C150  VDC_V: 1.5kV  ValueDisplayed: 0.01uF  [1812]  (hidden comment: 1812SC103KAT1A)
D12  TPD1E1B04DPYR  [DPY0002A]  (value not drawn)
D13  TPD1E1B04DPYR  [DPY0002A]  (value not drawn)
D14  TPD1E1B04DPYR  [DPY0002A]  (value not drawn)
D15  TPD1E1B04DPYR  [DPY0002A]  (value not drawn)
J7  615108137421R  [FP-615108137421R_CONN_JACK_16MM4_15MM7-MFG]
J8  7781  [Keystone_7781]
L6  742792062  [0805_HV]
L7  742792062  [0805_HV]
L8  742792062  [0805_HV]
Q4  MOSFET_N_D3G1S2_PD2  [YJC0003A]  (value not drawn)
Q5  MOSFET_N_D3G1S2_PD2  [YJC0003A]  (value not drawn)
R213  ValueDisplayed: 2.49k  [0402]  (hidden comment: CRCW04022K49FKED)
R214  Value1: 1%  ValueDisplayed: 2.49k  [0402]  (hidden comment: CRCW04022K49FKED)
R215  Value1: 1%  ValueDisplayed: 2.49k  [0402]  (hidden comment: CRCW04022K49FKED)
R216  Value1: 1%  ValueDisplayed: 2.49k  [0402]  (hidden comment: CRCW04022K49FKED)
R217  Value1: 1%  ValueDisplayed: 2.49k  [0402]  (hidden comment: CRCW04022K49FKED)
R218  Value1: 1%  ValueDisplayed: 2.49k  [0402]  (hidden comment: CRCW04022K49FKED)
R219  Value1: 1%  ValueDisplayed: 2.49k  [0402]  (hidden comment: CRCW04022K49FKED)
R221  Value1: 1%  ValueDisplayed: 2.49k  [0402]  (hidden comment: CRCW04022K49FKED)
R222  Value1: 1%  ValueDisplayed: 2.49k  [0402]  (hidden comment: CRCW04022K49FKED)
R223  Value1: 1%  ValueDisplayed: 2.49k  [0402]  (hidden comment: CRCW04022K49FKED)
R224  Value1: 1%  ValueDisplayed: 2.49k  [0402]  (hidden comment: CRCW04022K49FKED)
R225  Value1: 1%  ValueDisplayed: 2.49k  [0402]  (hidden comment: CRCW04022K49FKED)
R226  Value1: 1%  ValueDisplayed: 2.49k  [0402]  (hidden comment: CRCW04022K49FKED)
R227  Value1: 1%  ValueDisplayed: 2.49k  [0402]  (hidden comment: CRCW04022K49FKED)
R228  ValueDisplayed: 22  [0402L]  (hidden comment: CRCW040222R0JNED)
R229  ValueDisplayed: 75.0  [0805_HV]  (hidden comment: CRCW080575R0FKEA)
R230  ValueDisplayed: 22  [0402L]  (hidden comment: CRCW040222R0JNED)
R231  ValueDisplayed: 75.0  [0805_HV]  (hidden comment: CRCW080575R0FKEA)
R232  ValueDisplayed: 200  [0402]  (hidden comment: CRCW0402200RFKED)
R233  ValueDisplayed: 22  [0402L]  (hidden comment: CRCW040222R0JNED)
R234  ValueDisplayed: 22  [0402L]  (hidden comment: CRCW040222R0JNED)
R235  ValueDisplayed: 11.0k  [0402]  (hidden comment: CRCW040211K0FKED)
R237  ValueDisplayed: 22  [0402L]  (hidden comment: CRCW040222R0JNED)
R238  ValueDisplayed: 22  [0402L]  (hidden comment: CRCW040222R0JNED)
R239  ValueDisplayed: 200  [0402]  (hidden comment: CRCW0402200RFKED)
R240  ValueDisplayed: 1.0k  [0402]  (hidden comment: CRCW04021K00JNED)
R242  ValueDisplayed: 2.20k  [0402L]  (hidden comment: CRCW04022K20FKED)
R243  ValueDisplayed: 2.20k  [0402L]  (hidden comment: CRCW04022K20FKED)
R244  ValueDisplayed: 1.0k  [0402]  (hidden comment: CRCW04021K00JNED)
R245  ValueDisplayed: 75.0  [0805_HV]  (hidden comment: CRCW080575R0FKEA)
R246  ValueDisplayed: 0  [0402]  (hidden comment: CRCW04020000Z0ED)
R248  ValueDisplayed: 75.0  [0805_HV]  (hidden comment: CRCW080575R0FKEA)
R249  ValueDisplayed: 1.0M  [2010]  (hidden comment: CRCW20101M00JNEF)
R250  ValueDisplayed: 1.0k  [0402]  (hidden comment: CRCW04021K00JNED)
R251  ValueDisplayed: 1.0k  [0402]  (hidden comment: CRCW04021K00JNED)
R252  ValueDisplayed: 1.0M  [2010]  (hidden comment: CRCW20101M00JNEF)
R305  ValueDisplayed: 0  [0402]  (hidden comment: CRCW04020000Z0ED)
T1  749020011A  [FP-749020011A_SMT_17MM5_14MM2-MFG]
TP10  TESTPOINT  [TP_25MIL-SMT]  (value not drawn)  (no BOM)
TP11  TESTPOINT  [TP_25MIL-SMT]  (value not drawn)  (no BOM)
TP12  TESTPOINT  [TP_25MIL-SMT]  (value not drawn)  (no BOM)
TP14  TESTPOINT  [TP_25MIL-SMT]  (value not drawn)  (no BOM)
TP31  TESTPOINT  [TP_25MIL-SMT]  (value not drawn)  (no BOM)
TP32  TESTPOINT  [TP_25MIL-SMT]  (value not drawn)  (no BOM)
TP33  TESTPOINT  [TP_25MIL-SMT]  (value not drawn)  (no BOM)
U31  DP83869HMRGZT  [RGZ0048B-MFG]
U32  TPD2E2U06DRLR  [DRL0005A]
U33  TPD2E2U06DRLR  [DRL0005A]
U34  TPD2E2U06DRLR  [DRL0005A]
U35  TPD2E2U06DRLR  [DRL0005A]

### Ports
CLKOUT0 (in), ETH1_RGMII1_RD0 (out), ETH1_RGMII1_RD1 (out), ETH1_RGMII1_RD2 (out), ETH1_RGMII1_RD3 (out), ETH1_RGMII1_RX_CTL (in), ETH1_RGMII1_RX_ER (out), ETH1_RGMII1_RXC (in), ETH1_RGMII1_TD0 (in), ETH1_RGMII1_TD1 (in), ETH1_RGMII1_TD2 (in), ETH1_RGMII1_TD3 (in), ETH1_RGMII1_TX_CTL (in), ETH1_RGMII1_TXC (in), PHY1_CLK_IN (in), PHY1_LINK (out), PHY1_RESET (in), PHY_INT (in), PHY_MDC (in), PHY_MDIO (out)

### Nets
1V1: L8.2
1V1_ETH1: C116.1 C117.1 C118.1 C119.1 C123.1 C129.1 C130.1 C131.1 L8.1 U31.6(VDD1P1) U31.31(VDD1P1) U31.39(VDD1P1)
1V8: L6.2
2V5: L7.2
2V5_ETH1: C113.1 C114.1 C115.1 C122.1 C127.1 C128.1 L7.1 U31.3(VDDA2P5) U31.9(VDDA2P5)
3V3: R240.2 R244.1
EARTH_GND: C141.2 C150.1 J7.13(MNT_1) J7.14(MNT_2) J8.1 J8.2 J8.3 J8.4 R249.1 R252.2
GND: C109.2 C110.2 C111.2 C113.2 C114.2 C115.2 C116.2 C117.2 C118.2 C119.2 C121.2 C122.2 C123.2 C124.2 C125.2 C127.2 C128.2 C129.2 C130.2 C131.2 C133.2 C134.2 C136.1 C137.2 C138.2 C139.1 C140.2 C142.1 C143.1 C144.1 C145.1 C146.1 C147.1 C148.1 C149.1 C150.2 D12.1 D13.1 D14.1 D15.1 Q4.2(S) Q5.2(S) R221.1 R222.1 R223.1 R224.1 R225.1 R226.1 R227.1 R235.2 R252.1 U31.49(GND) U32.4(GND) U33.4(GND) U34.4(GND) U35.4(GND)
VCC_ETH1: C109.1 C110.1 C111.1 C121.1 C124.1 C125.1 L6.1 R213.2 R214.2 R215.2 R216.2 R217.2 R218.2 R219.2 R242.1 R243.1 U31.18(VDDIO) U31.30(VDDIO)
CLKOUT0: R305.1 ; port CLKOUT0
E1_TD_A_N: J7.7 T1.14(MX4+)
E1_TD_A_P: J7.8 T1.13(MX4-)
E1_TD_B_N: J7.4 T1.17(MX3+)
E1_TD_B_P: J7.5 T1.16(MX3-)
E1_TD_C_N: J7.3 T1.20(MX2+)
E1_TD_C_P: J7.6 T1.19(MX2-)
E1_TD_D_N: J7.1 T1.23(MX1+)
E1_TD_D_P: J7.2 T1.22(MX1-)
ETH1_GPIO_1: R219.1 R227.2 U31.22(JTAG_TDO/GPIO_1) ; off-sheet ETH1_GPIO_1
ETH1_LED_0: R216.1 R224.2 R251.1 TP31.1 U31.47(LED_0) ; off-sheet ETH1_LED_0, port PHY1_LINK
ETH1_LED_1: R217.1 R225.2 R228.1 U31.46(LED_1/RX_ER) ; off-sheet ETH1_LED_1
ETH1_LED_2: R218.1 R226.2 R250.1 U31.45(LED_2/GPIO_0) ; off-sheet ETH1_LED_2
ETH1_RGMII1_RD0: R213.1 R221.2 R233.1 ; off-sheet ETH1_RGMII1_RD0, port ETH1_RGMII1_RD0
ETH1_RGMII1_RD1: R214.1 R222.2 R234.1 ; off-sheet ETH1_RGMII1_RD1, port ETH1_RGMII1_RD1
ETH1_RGMII1_RD2: R237.1 ; port ETH1_RGMII1_RD2
ETH1_RGMII1_RD3: R238.1 ; port ETH1_RGMII1_RD3
ETH1_RGMII1_RX_CTL: R215.1 R223.2 TP33.1 U31.38(RX_CTRL/RX_DV) ; off-sheet ETH1_RGMII1_RX_CTL, port ETH1_RGMII1_RX_CTL
ETH1_RGMII1_RX_ER: R228.2 ; port ETH1_RGMII1_RX_ER
ETH1_RGMII1_RXC: R230.1 TP12.1 ; port ETH1_RGMII1_RXC
ETH1_RGMII1_TD0: U31.28(TX_D0) ; port ETH1_RGMII1_TD0
ETH1_RGMII1_TD1: U31.27(TX_D1) ; port ETH1_RGMII1_TD1
ETH1_RGMII1_TD2: U31.26(TX_D2) ; port ETH1_RGMII1_TD2
ETH1_RGMII1_TD3: U31.25(TX_D3) ; port ETH1_RGMII1_TD3
ETH1_RGMII1_TX_CTL: TP11.1 U31.37(TX_CTRL/TX_EN) ; port ETH1_RGMII1_TX_CTL
ETH1_RGMII1_TXC: TP10.1 U31.29(GTX_CLK/TX_CLK) ; port ETH1_RGMII1_TXC
ETH1_TD_A_N: C143.2 T1.11(TD4+) U31.2(TD_M_A) U32.2(NC) U32.5(IO2) ; off-sheet ETH1_TD_A_N
ETH1_TD_A_P: C142.2 T1.12(TD4-) U31.1(TD_P_A) U32.3(IO1) ; off-sheet ETH1_TD_A_P
ETH1_TD_B_N: C145.2 T1.8(TD3+) U31.5(TD_M_B) U33.2(NC) U33.5(IO2) ; off-sheet ETH1_TD_B_N
ETH1_TD_B_P: C144.2 T1.9(TD3-) U31.4(TD_P_B) U33.3(IO1) ; off-sheet ETH1_TD_B_P
ETH1_TD_C_N: C147.2 T1.5(TD2+) U31.8(TD_M_C) U34.2(NC) U34.5(IO2) ; off-sheet ETH1_TD_C_N
ETH1_TD_C_P: C146.2 T1.6(TD2-) U31.7(TD_P_C) U34.3(IO1) ; off-sheet ETH1_TD_C_P
ETH1_TD_D_N: C149.2 T1.2(TD1+) U31.11(TD_M_D) U35.2(NC) U35.5(IO2) ; off-sheet ETH1_TD_D_N
ETH1_TD_D_P: C148.2 T1.3(TD1-) U31.10(TD_P_D) U35.3(IO1) ; off-sheet ETH1_TD_D_P
PHY1_CLK_IN: R246.1 ; port PHY1_CLK_IN
PHY1_RESET: R243.2 TP32.1 U31.43(~{RESET}) ; port PHY1_RESET
PHY_INT: R242.2 U31.44(~{INT}/~{PWDN}) ; port PHY_INT
PHY_MDC: U31.42(MDC) ; port PHY_MDC
PHY_MDIO: U31.41(MDIO) ; port PHY_MDIO
NetC133_1: C133.1 T1.1(TCT1)
NetC134_1: C134.1 T1.4(TCT2)
NetC136_2: C136.2 D14.2 J7.10(Green_Anode) R240.1
NetC137_1: C137.1 T1.7(TCT3)
NetC138_1: C138.1 R246.2 R305.2 U31.20(XI)
NetC139_2: C139.2 D15.2 J7.12(Yellow_Anode) R244.2
NetC140_1: C140.1 T1.10(TCT4)
NetC141_1: C141.1 R229.2 R231.2 R245.2 R248.2 R249.2
NetD12_2: D12.2 J7.11(Yellow_Cathode) R239.2
NetD13_2: D13.2 J7.9(Green_Cathode) R232.2
NetQ4_1: Q4.1(G) R250.2
NetQ4_3: Q4.3(D) R239.1
NetQ5_1: Q5.1(G) R251.2
NetQ5_3: Q5.3(D) R232.1
NetR229_1: R229.1 T1.24(MCT1)
NetR230_2: R230.2 U31.32(RX_CLK)
NetR231_1: R231.1 T1.21(MCT2)
NetR233_2: R233.2 U31.33(RX_D0)
NetR234_2: R234.2 U31.34(RX_D1)
NetR235_1: R235.1 U31.12(RBIAS)
NetR237_2: R237.2 U31.35(RX_D2)
NetR238_2: R238.2 U31.36(RX_D3)
NetR245_1: R245.1 T1.18(MCT3)
NetR248_1: R248.1 T1.15(MCT4)
NetTP14_1: TP14.1 U31.40(CLK_OUT)

Not connected (* = marked no-connect by the designer): U31 13(VDDA1P8_1)* 14(SON)* 15(SOP)* 16(SIP)* 17(SIN)* 19(XO) 21(JTAG_CLK/TX_ER)* 23(JTAG_TMS)* 24(JTAG_TDI/SD)* 48(VDDA1P8_2)*; U32 1(NC)*; U33 1(NC)*; U34 1(NC)*; U35 1(NC)*

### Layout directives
differential pair: E1_TD_A_N, E1_TD_A_P, E1_TD_B_N, E1_TD_B_P, E1_TD_C_N, E1_TD_C_P, E1_TD_D_N, E1_TD_D_P, ETH1_TD_A_N, ETH1_TD_A_P, ETH1_TD_B_N, ETH1_TD_B_P, ETH1_TD_C_N, ETH1_TD_C_P, ETH1_TD_D_N, ETH1_TD_D_P

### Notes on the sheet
- Mode 0
- (near R215) Mode 0
- Mode 1
- ETH1 Default:
  Address 0x0;
  AutoNeg Enable;
  10/100/1000;
  Mirror Enable
- ESD prodection
- (near R250) Yellow LED - activity
- (near R251) Green LED - LINK
- ETH1

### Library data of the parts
C109 C113 C116 = CMP-0008706-2: CAP, CERM, 10 uF, 35 V, +/- 20%, X7R, 1206_190; Manufacturer: TDK; Polarized: N; Value: 10uF; U/M: EA; Cap_F: 10µF; Value1: Unknown; VDC_V: 35V; TaMin_C: -55°C; TaMax_C: 125°C; Cap_Case: 1206; AEC Category: Q200; SizeArea_mm2: 5.12; SizeAreaWB_mm2: 10.92; SizeX_mm: 3.2; SizeY_mm: 1.6; SizeZ_mm: 1.9
C110 C111 C114 C115 C117-C119 = CMP-0009670-3: CAP, CERM, 0.1 uF, 16 V, +/- 10%, X5R, 0201; Manufacturer: MuRata; TaMin_C: -55°C; Polarized: N; SizeAreaWB_mm2: 2.08; Value1: Unknown; U/M: EA; Value: 0.1uF; TaMax_C: 125°C; SizeZ_mm: 0.33; SizeX_mm: 0.6; SizeY_mm: 0.3; Cap_Case: 0201; SizeArea_mm2: 0.18; Cap_F: 100nF; AEC Category: Q200
C121-C123 = CMP-0006227-2: CAP, CERM, 0.01 uF, 16 V, +/- 10%, X7R, 0402; Manufacturer: Wurth Elektronik; TaMin_C: -55°C; Polarized: N; SizeAreaWB_mm2: 3; Value1: Unknown; U/M: EA; Value: 0.01uF; TaMax_C: 125°C; SizeZ_mm: 0.6; SizeX_mm: 1; SizeY_mm: 0.5; Cap_F: 10nF; AEC Category: Q200
C124 C125 C127-C131 = CMP-0064909-1: CAP, CERM, 1 uF, 10 V,+/- 20%, X5R, 0201; Manufacturer: MuRata; TaMin_C: -55°C; Polarized: N; SizeAreaWB_mm2: 2.08; Value1: Unknown; U/M: EA; Value: 1uF; TaMax_C: 85°C; SizeZ_mm: 0.26; SizeX_mm: 0.6; SizeY_mm: 0.3; SizeArea_mm2: 0.18; Cap_F: 1µF; AEC Category: Q200
C133 C134 C137 C140 = CMP-0006641-2: CAP, CERM, 0.1 uF, 16 V, +/- 10%, X7R, 0402; Manufacturer: MuRata; TaMin_C: -55°C; Polarized: N; SizeAreaWB_mm2: 3; Value1: Unknown; U/M: EA; Value: 0.1uF; TaMax_C: 125°C; SizeZ_mm: 0.6; SizeX_mm: 1; SizeY_mm: 0.5; Value2: 16V; Cap_F: 100nF; AEC Category: Q200
C136 C139 = CMP-0006221-2: CAP, CERM, 0.1 uF, 10 V, +/- 20%, X5R, 0402; Manufacturer: Wurth Elektronik; TaMin_C: -55°C; Polarized: N; SizeAreaWB_mm2: 3; Value1: Unknown; U/M: EA; Value: 0.1uF; TaMax_C: 85°C; SizeZ_mm: 0.6; SizeX_mm: 1; SizeY_mm: 0.5; Value2: 10V; Cap_F: 100nF; AEC Category: Q200
C138 = CMP-0006311-2: CAP, CERM, 22 pF, 50 V, +/- 5%, C0G/NP0, AEC-Q200 Grade 1, 0402; Manufacturer: TDK; TaMin_C: -55°C; Polarized: N; SizeAreaWB_mm2: 3; Value1: Unknown; U/M: EA; Value: 22pF; TaMax_C: 125°C; SizeZ_mm: 0.6; SizeX_mm: 1; SizeY_mm: 0.5; Cap_Case: 0402; AEC Qualified: Y; AEC Category: Q200
C141 = CMP-0009436-2: CAP, CERM, 1000 pF, 2000 V, +/- 10%, X7R, 1808; Manufacturer: MuRata; TaMin_C: -55°C; Polarized: N; SizeAreaWB_mm2: 16.5; Value1: Unknown; U/M: EA; Value: 1000pF; TaMax_C: 125°C; SizeZ_mm: 2.03; SizeX_mm: 4.5; SizeY_mm: 2; Value2: 2000V; SizeArea_mm2: 9; Cap_F: 1nF; AEC Category: Q200
C142-C149 = CMP-0009667-3: CAP, CERM, 4.7 pF, 50 V, +/- 5%, C0G/NP0, 0201; Manufacturer: MuRata; Polarized: N; Value: 4.7pF; U/M: EA; Value1: Unknown; VDC_V: 50V; TaMin_C: -55°C; TaMax_C: 125°C; Cap_Case: 0201; AEC Category: Q200; SizeArea_mm2: 0.18; SizeAreaWB_mm2: 2.08; SizeX_mm: 0.6; SizeY_mm: 0.3; SizeZ_mm: 0.26
C150 = CMP-0009297-1: CAP, CERM, 0.01 uF, 1500 V, +/- 10%, X7R, 1812; Manufacturer: AVX; TaMin_C: -55°C; ESR_ohm: 0.05; Polarized: N; SizeAreaWB_mm2: 23.1; Value1: 0.05 ohm; U/M: EA; Value: 0.01uF; TaMax_C: 125°C; SizeZ_mm: 1.35; SizeX_mm: 4.5; SizeY_mm: 3.2; Value2: 1500V; SizeArea_mm2: 14.4; Cap_F: 10nF; AEC Category: Q200
D12-D15 = CMP-0073609-3: 1-Channel ESD Protection Diode With Low Dynamic Resistance and Low Clamping Voltage, DPY0002A (X1SON-2); PartNumber: TPD1E1B04DPYT; Manufacturer: Texas Instruments; SizeX_mm: 1.0; Rating: Catalog; SizeY_mm: 0.6; SizeAreaWB_mm2: 3.2; SizeZ_mm: 0.45; AEC Category: Q200; CompType: IC
J7 = CMP-0087236-1: WR-MJ Modular Jack THR Horizontal Shielded w. LED and EMI Finger 8P8C Tab Up; Manufacturer: Wurth Electronics Inc.; Current_A: 1.5A; ContactFinish: Gold; Shrouded: true; Voltage_V: 125V
J8 = CMP-0078815-1: Screw Terminal, R/A; Manufacturer: Keystone; Current_A: 15A; ContactFinish: Tin; Row_Count: 2
L6-L8 = CMP-0003092-1: Ferrite Bead, 80 ohm @ 100 MHz, 0.5 A, 0805; Manufacturer: Wurth Elektronik; Ztyp@1GHz_Ohm: 146.576; ZTyp@100MHz_Ohm: 80; SizeAreaWB_mm2: 6.75; DCR_ohm: 0.2; Value1: 0.2 ohm; Value: 80 ohm; Imax_A: 500mA; SizeZ_mm: 1.45; SizeX_mm: 2; SizeY_mm: 1.25; Value2: 0.5A; SizeArea_mm2: 2.5
Q4 Q5 = CMP-0000198-1: MOSFET, N-CH, 12 V, 2.9 A, YJC0003A (PICOSTAR-3); PartNumber: CSD13383F4; Manufacturer: Texas Instruments; Alternate Manufacturer: None; U/M: EA; ChType: N; Value: 12V; Value1: 0.04; Rdson45_ohm: 0.044; Value2: 2 nC; QgTyp_nC: 2; Vgs_V: 10V; IdsMax_A: 2.9A; AEC Category: Q101; SizeArea_mm2: 0.657225; SizeAreaWB_mm2: 3.327225; SizeX_mm: 1.035; SizeY_mm: 0.635; SizeZ_mm: 0.35
R213 = CMP-0026237-2: RES, 2.49 k, 1%, 0.063 W, AEC-Q200 Grade 0, 0402; Manufacturer: Vishay-Dale; Power_W: 63mW; TempCo: 100 ppm/C; Value_Code: 2k49; Value: 2.49k; EIA_Code: E96; SizeX_mm: 1; SizeY_mm: 0.5; SizeZ_mm: 0.6; Value2: 0.063W; AEC Qualified: Y; VDC_V: 50V; AEC Category: Q200; AEC Grade: 0
R214-R219 R221-R227 = CMP-0026237-2: RES, 2.49 k, 1%, 0.063 W, AEC-Q200 Grade 0, 0402; Manufacturer: Vishay-Dale; Power_W: 63mW; TempCo: 100 ppm/C; Value_Code: 2k49; Value: 2.49k; EIA_Code: E96; SizeX_mm: 1; SizeY_mm: 0.5; SizeZ_mm: 0.6; Value2: 0.063W; AEC Qualified: Y; VDC_V: 50V; AEC Grade: 0; AEC Category: Q200
R228 R230 R233 R234 R237 R238 = CMP-0026880-3: as R133-R144 on sheet TIDA-010948-CB-PWM
R229 R231 R245 R248 = CMP-0021425-3: RES, 75.0, 1%, 0.125 W, AEC-Q200 Grade 0, 0805; Manufacturer: Vishay-Dale; Power_W: 125mW; TempCo: 100 ppm/C; Value_Code: 75R0; Value: 75.0; EIA_Code: E96; Res_ohm: 75; SizeX_mm: 2; SizeY_mm: 1.25; SizeZ_mm: 1.45; Value2: 0.125W; SizeArea_mm2: 2.5; AEC Qualified: Y; VDC_V: 150V; AEC Category: Q200; AEC Grade: 0
R232 R239 = CMP-0026159-2: RES, 200, 1%, 0.063 W, AEC-Q200 Grade 0, 0402; Manufacturer: Vishay-Dale; Power_W: 63mW; TempCo: 100 ppm/C; Value_Code: 200R; Value: 200; EIA_Code: E96; SizeX_mm: 1; SizeY_mm: 0.5; SizeZ_mm: 0.6; Value2: 0.063W; AEC Qualified: Y; VDC_V: 50V; AEC Category: Q200; AEC Grade: 0
R235 = CMP-0025975-3: RES, 11.0 k, 1%, 0.063 W, AEC-Q200 Grade 0, 0402; Manufacturer: Vishay-Dale; Power_W: 63mW; TempCo: 100 ppm/C; Value_Code: 11k0; Value: 11.0k; EIA_Code: E96; Res_ohm: 11k; SizeX_mm: 1; SizeY_mm: 0.5; SizeZ_mm: 0.6; Value2: 0.063W; AEC Qualified: Y; VDC_V: 50V; AEC Category: Q200; AEC Grade: 0
R240 R244 R250 R251 = CMP-0026852-1: RES, 1.0 k, 5%, 0.063 W, 0402; Manufacturer: Vishay-Dale; Power_W: 63mW; TempCo: 200 ppm/C; Value_Code: 1k00; U/M: EA; Value: 1.0k; EIA_Code: E24; Res_ohm: 1k; SizeX_mm: 1; SizeY_mm: 0.5; SizeZ_mm: 0.6; Value2: 0.063W; VDC_V: 50V; AEC Category: Q200
R242 R243 = CMP-0026231-2: RES, 2.20 k, 1%, 0.063 W, AEC-Q200 Grade 0, 0402; Manufacturer: Vishay-Dale; Power_W: 63mW; TempCo: 100 ppm/C; Value_Code: 2k20; Value: 2.20k; Res_ohm: 2.2k; SizeX_mm: 1; SizeY_mm: 0.5; SizeZ_mm: 0.6; Value2: 0.063W; AEC Qualified: Y; AEC Category: Q200; AEC Grade: 0
R246 R305 = CMP-0026822-3: RES, 0, 5%, 0.063 W, AEC-Q200 Grade 0, 0402; Manufacturer: Vishay-Dale; Power_W: 63mW; TempCo: 200 ppm/C; Value_Code: 0000; Value: 0; EIA_Code: E24; SizeX_mm: 1; SizeY_mm: 0.5; SizeZ_mm: 0.6; Value2: 0.063W; AEC Qualified: Y; VDC_V: 50V; AEC Category: Q200
R249 R252 = CMP-0016081-3: RES, 1.0 M, 5%, 0.75 W, AEC-Q200 Grade 0, 2010; Manufacturer: Vishay-Dale; Power_W: 750mW; TempCo: 200 ppm/C; Value_Code: 1M00; Value: 1.0Meg; EIA_Code: E24; Res_ohm: 1M; SizeX_mm: 5; SizeY_mm: 2.5; SizeZ_mm: 1.66; Value2: 0.75W; SizeArea_mm2: 12.5; AEC Qualified: Y; VDC_V: 400V; AEC Grade: 0; AEC Category: Q200
T1 = CMP-0086582-1: WURTH ELEKTRONIK LAN TRANSFORMER, 10/100/1000 BASE-T; Manufacturer: Wurth Electronics; Ind_H: 350µH; SizeZ_mm: 6.5mm; AEC Qualified: No; Ns1toNp: 1:1
TP10-TP12 TP14 TP31-TP33 = CMP-0078143-3: TEST POINT.  No entry in BOM.
U31 = CMP-0091377-1: 1/1 Transceiver Ethernet 48-VQFN (7x7); Manufacturer: Texas Instruments; TaMin_C: -40°C; SizeZ_mm: 1mm; TaMax_C: +125°C; Max Supply Voltage: 3.45V; Number Of Channels: 1; AEC Qualified: No; Data Rate: 1000Mbits/s; Min Supply Voltage: 990mV; Simplex Duplex: Full-Duplex; Standoff Height: 0mm
U32-U35 = CMP-0066602-2: Dual-Channel High-Speed ESD Protection, DRL0005A (SOT-OTHER-5); Alternate Manufacturer: Texas Instruments; Green_Lifecycle: Active; SizeAreaWB_mm2: 6.76; Green_REACh: Passed; U/M: EA; SizeZ_mm: 0.6; SizeX_mm: 1.6; SizeArea_mm2: 2.56; CompType: IC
